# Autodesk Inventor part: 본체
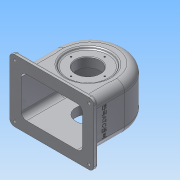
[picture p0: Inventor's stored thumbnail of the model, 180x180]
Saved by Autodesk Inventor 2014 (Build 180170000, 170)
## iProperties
Created: 2016-01
Part Number: 본체
Material: 알루미늄 6061
Document SubType Name: Modeling
Designer: net
Density: 2.71 g/cm^3
Appearance: 알루미늄 - 평지
Mass: 809.574 g
Surface Area: 999.745 cm^2
Volume: 298.736 cm^3
Author: net
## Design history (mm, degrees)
sketch "스케치1"
  geometry: L1 (-57, -64)-(57, -64); L2 (57, -64)-(57, 57); L3 (57, 57)-(-57, 57); L4 (-57, 57)-(-57, -64); 2 further points
  constraints: 8 end point, 2 parallel, 1 horizontal, 1 midpoint, 1 perpendicular, 1 vertical alignment
  dimensions: "d0" = 114 distance of L1.start L1.end; "d1" = 121 distance of L1.end L2.end; "d2" = 64 distance from line of L1 point (0, 0)
extrude "돌출1" new body sketch "스케치1" stored distance "d3" = 77; taper "d4" = 0 deg
fillet "모깎기1" dims "d5" = 57
fillet "모깎기2" dims "d6" = 14
sketch "스케치2"
  geometry: L1 (86, 0)-(0, 0) reference; L2 (100, 14)-(100, 63) reference; L3 (0, 77)-(86, 77) reference; L4 (-14, 63)-(-14, 14) reference; L5 (-19, 90.5)-(105, 90.5); L6 (113, 82.5)-(113, -5.5); L7 (105, -13.5)-(-19, -13.5); L8 (-27, -5.5)-(-27, 82.5); C1 r 2.5 at (-19, 82.5); C2 r 2.5 at (-19, -5.5); C3 r 2.5 at (105, -5.5); C4 r 2.5 at (105, 82.5); A1 r 14 centre (0, 14) between (-14, 14) and (0, 0) reference; A2 r 14 centre (86, 14) between (86, 0) and (100, 14) reference; A3 r 14 centre (86, 63) between (100, 63) and (86, 77) reference; A4 r 14 centre (0, 63) between (0, 77) and (-14, 63) reference; A5 r 8 centre (-19, 82.5) between (-19, 90.5) and (-27, 82.5); A6 r 8 centre (-19, -5.5) between (-27, -5.5) and (-19, -13.5); A7 r 8 centre (105, -5.5) between (105, -13.5) and (113, -5.5); A8 r 8 centre (105, 82.5) between (113, 82.5) and (105, 90.5); 8 further points
  constraints: 8 centre point, 8 end point, 8 point on circle, 8 tangent, 6 point on line, 4 coincident, 4 midpoint, 3 equal radius, 2 parallel, 1 horizontal, 1 horizontal alignment, 1 perpendicular, 1 vertical alignment
  dimensions: "d7" = 140 distance of point (-27, 90.5) point (113, 90.5); "d8" = 104 distance of point (113, 90.5) point (113, -13.5); "d9" = 8 radius of A5; "d10" = 8 radius of A6; "d11" = 8 radius of A7; "d12" = 8 radius of A8; "d13" = 5 diameter of C1
extrude "돌출2" join sketch "스케치2" distance "d14" = 7; taper "d15" = 0 deg
sketch "스케치4"
  geometry: L1 (-57, -57)-(-57, 0) reference; L2 (57, 0)-(57, -57) reference; L3 (-51, -64)-(-51, 0); L4 (51, 0)-(51, -64); L5 (-62, -64)-(62, -64) reference; A1 r 57 centre (0, 0) between (57, 0) and (-57, 0) reference; A2 r 51 centre (0, 0) between (51, 0) and (-51, 0); 1 further point
  constraints: 4 end point, 2 point on circle, 2 point on line, 1 centre point
  dimensions: "d21" = 6 radial gap between concentric circles of A2 A1; "d22" = 6 distance between parallel lines of L2 L4; "d23" = 6 distance between parallel lines of L1 L3
extrude "돌출3" cut sketch "스케치4" stored distance "d24" = 67; taper "d25" = 0 deg
fillet "모깎기3" dims "d26" = 9
node "작업 평면1"
sketch "스케치5"
  geometry: C1 r 6 at (-62, 52); 1 further point
  constraints: 1 centre point, 1 coincident
  dimensions: "d28" = 12 diameter of C1
extrude "돌출4" join sketch "스케치5" stored distance "d29" = 67; taper "d30" = 0 deg
fillet "모깎기4" dims "d31" = 3
hole "구멍1" diameter "d34" = 4.459; stored, may be unused: countersink angle "d38" = 90 deg, drill point angle "d40" = 0 deg; dims "d32" = 10, "d33" = 10, "d35" = 6, "d36" = 4, "d37" = 2, "d39" = 8
sketch "스케치11"
  geometry: L1 (42, 33.5)-(0, 33.5) reference; L2 (0, 38.5)-(43, 38.5) reference; L3 (0, 33.5)-(-64, 33.5) reference; L4 (-57, 38.5)-(0, 38.5) reference; L5 (-4, 38.5)-(-4, 19.5); L6 (-4, 19.5)-(24, 19.5); L7 (24, 19.5)-(39.943, 38.5); L8 (39.943, 38.5)-(-4, 38.5); L9 (33.416, 38.5)-(30.899, 35.5); L10 (30.899, 35.5)-(-4, 35.5); L11 (-64, -24.5)-(-64, 24.5) reference; 1 further point
  constraints: 12 end point, 4 point on line, 2 horizontal, 1 parallel, 1 vertical
  dimensions: "d112" = 56 diameter of L6.end L5; "d113" = 3 distance between parallel lines of L10 L2; "d114" = 5 distance between parallel lines of L9 L7; "d115" = 16 distance between parallel lines of L6 L10; "d116" = 50 deg angle of L6 L7; "d117" = 60 distance between parallel lines of L11 L5
revolve "회전3" stored, may be unused: angle "d118" = 90 deg
revolve "회전4" stored, may be unused: angle "d119" = 90 deg
sketch "스케치12"
  geometry: L1 (62, -64)-(-62, -64) reference; C1 r 31 at (0, -4); A1 r 43 centre (0, 0) between (43, 0) and (-43, 0) reference
  constraints: 1 centre point, 1 vertical alignment
  dimensions: "d120" = 62 diameter of C1; "d121" = 60 distance from line of L1 C1.centre
extrude "돌출6" join sketch "스케치12" distance "d122" = 10; taper "d123" = 0 deg
hole "구멍6" diameter "d126" = 40; stored, may be unused: countersink angle "d130" = 90 deg, drill point angle "d132" = 0 deg; dims "d124" = 10, "d125" = 10, "d127" = 6, "d128" = 4, "d129" = 2, "d131" = 15
hole "구멍7" diameter "d135" = 40; stored, may be unused: countersink angle "d139" = 90 deg, drill point angle "d141" = 0 deg; dims "d133" = 10, "d134" = 10, "d136" = 6, "d137" = 4, "d138" = 2, "d140" = 15
fillet "모깎기10" dims "d142" = 3
fillet "모깎기11" dims "d143" = 1
fillet "모깎기12" dims "d144" = 3
chamfer "모따기2" distance "d145" = 1; stored, may be unused: second distance "d146" = 2, angle "d147" = 45 deg
sketch "스케치13"
  geometry: L1 (68.5, -64)-(-19.5, -64) reference; L2 (-14, -13.054)-(-14, -56) reference; 2 further points
  constraints: 1 other
  dimensions: "d148" = 30 distance from line of L1 point (24.5, -34); "d149" = 38.5 distance from line of point (24.5, -34) L2
feature "엠보싱2" sketch "스케치13" dims "d150" = 0.5, "d151" = 0
sketch "스케치14"
  geometry: C1 r 33.5 at (0, 0) reference; 2 further points
  constraints: 1 vertical alignment
  dimensions: "d152" = 28 distance of C1.centre point (0, 28)
hole "구멍8" sketch "스케치14" at (0, 28) diameter "d153" = 2.459; stored, may be unused: countersink angle "d157" = 90 deg, drill point angle "d159" = 118 deg; dims "d154" = 7, "d155" = 4, "d156" = 2, "d158" = 9
sketch "스케치15"
  geometry: C1 r 31 at (0, 0) reference; 2 further points
  constraints: 1 vertical alignment
  dimensions: "d163" = 24 distance of C1.centre point (0, 24)
hole "구멍9" sketch "스케치15" at (0, 24) diameter "d164" = 2.459; stored, may be unused: countersink angle "d168" = 90 deg, drill point angle "d170" = 118 deg; dims "d165" = 6, "d166" = 4, "d167" = 2, "d169" = 8
sketch "스케치6"
  geometry: C1 r 31 at (0, 0); A1 r 43 centre (0, 0) between (43, 0) and (-43, 0) reference
  constraints: 1 centre point, 1 coincident
  dimensions: "d41" = 62 diameter of C1
extrude "돌출5" join sketch "스케치6" distance "d42" = 10; taper "d43" = 0 deg
fillet "모깎기5" dims "d44" = 3
hole "구멍2" diameter "d47" = 40; stored, may be unused: countersink angle "d51" = 90 deg, drill point angle "d53" = 0 deg; dims "d45" = 10, "d46" = 10, "d48" = 6, "d49" = 4, "d50" = 2, "d52" = 15
sketch "스케치7"
  geometry: L1 (42, 33.5)-(0, 33.5) reference; L2 (0, 38.5)-(43, 38.5) reference; L3 (-64, -24.5)-(-64, 24.5) reference; L4 (0, 33.5)-(-64, 33.5) reference; L5 (-57, 38.5)-(0, 38.5) reference; L6 (43, 38.5)-(27.057, 19.5); L7 (36.473, 38.5)-(33.956, 35.5); L8 (27.057, 19.5)-(-4, 19.5); L9 (0, 24.5)-(0, -24.5) reference; L10 (33.956, 35.5)-(-4, 35.5); L11 (43, 38.5)-(36.473, 38.5); L12 (-4, 38.5)-(-4, 19.5); L13 (36.473, 38.5)-(-4, 38.5); 2 further points
  constraints: 14 end point, 6 point on line, 4 horizontal, 1 parallel, 1 vertical
  dimensions: "d60" = 5 distance between parallel lines of L7 L6; "d61" = 3 distance between parallel lines of L10 L2; "d62" = 50 deg angle of L8 L6; "d65" = 16 distance between parallel lines of L8 L10; "d110" = 60 distance between parallel lines of L3 L12; "d111" = 0 distance from line of L2.end L6
revolve "회전1" stored, may be unused: angle "d66" = 90 deg
revolve "회전2" stored, may be unused: angle "d67" = 90 deg
hole "구멍3" diameter "d70" = 40; stored, may be unused: countersink angle "d74" = 90 deg, drill point angle "d76" = 0 deg; dims "d68" = 10, "d69" = 10, "d71" = 6, "d72" = 4, "d73" = 2, "d75" = 15
chamfer "모따기1" distance "d77" = 1; stored, may be unused: second distance "d78" = 2, angle "d79" = 45 deg
fillet "모깎기6" dims "d80" = 3
fillet "모깎기7" dims "d81" = 3
sketch "스케치8"
  geometry: C1 r 21 at (0, 0) reference; 1 further point
  constraints: 1 vertical alignment
  dimensions: "d82" = 28 distance of C1.centre point (0, 28)
hole "구멍4" sketch "스케치8" at (0, 28) diameter "d83" = 2.459; stored, may be unused: countersink angle "d87" = 90 deg, drill point angle "d89" = 118 deg; dims "d84" = 7, "d85" = 4, "d86" = 2, "d88" = 9
sketch "스케치9"
  geometry: C1 r 31 at (0, 0) reference; 1 further point
  constraints: 1 vertical alignment
  dimensions: "d93" = 24 distance of C1.centre point (0, 24)
hole "구멍5" sketch "스케치9" at (0, 24) diameter "d94" = 2.459; stored, may be unused: countersink angle "d98" = 90 deg, drill point angle "d100" = 118 deg; dims "d95" = 6, "d96" = 4, "d97" = 2, "d99" = 8
fillet "모깎기8" dims "d104" = 3
fillet "모깎기9" dims "d105" = 1
sketch "스케치10"
  geometry: L1 (68.5, -64)-(-19.5, -64) reference; L2 (-14, 0)-(-14, -56) reference; 3 further points
  constraints: 1 other
  dimensions: "d106" = 30 distance from line of L1 point (24.5, -34); "d107" = 38.5 distance from line of point (24.5, -34) L2
feature "엠보싱1" sketch "스케치10" dims "d108" = 0.5, "d109" = 0
node "솔리드1"
pattern_circular "원형 패턴3" dims angle "d161" = 360 deg
pattern_circular "원형 패턴4" dims angle "d172" = 360 deg
pattern_circular "원형 패턴1" dims angle "d91" = 360 deg
pattern_circular "원형 패턴2" dims angle "d102" = 360 deg
other parameters: "d27" = -127
